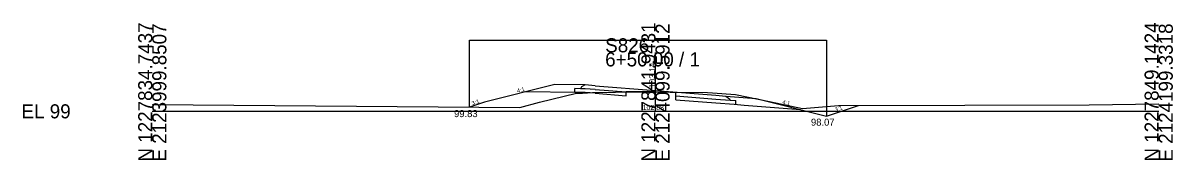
# Model space of a CAD drawing. Extents: x 2118382 to 2118616, y 1213030 to 1222057.
# Drawn here: x 2118381.9 to 2118610.4, y 1217030.1 to 1217057.4 of the extents above; entities that cross this region are included whole.
import ezdxf

# ---------------------------------------------------------------- set-up
doc = ezdxf.new("R2010")
doc.units = 0
for name, color, linetype in [('XS_CELL', 7, 'Continuous'), ('XS_M_DITCH', 7, 'Continuous'), ('XS_P_FINISHED_GRADE', 7, 'Continuous'), ('XS_P_FINISHED_GRADE_ELEV_TX', 7, 'Continuous'), ('XS_P_SUBGRADE_GRANULAR', 7, 'Continuous'), ('XS_P_SUBGRADE_LEVELING', 7, 'Continuous'), ('XS_P_SUBGRADE_PAVEMENT', 7, 'Continuous'), ('XS_P_TX_DCH', 7, 'Continuous'), ('XS_P_TX_FS_BS', 7, 'Continuous'), ('XS_X_GROUND', 7, 'Continuous'), ('XS_X_GROUND_TX', 7, 'Continuous')]:
    doc.layers.add(name, color=color, linetype=linetype)

msp = doc.modelspace()

# ---------------------------------------------------------------- linework, layer by layer
at = {"layer": 'XS_CELL'}
for p, q in [((2118507.6, 1217039.8), (2118507.6, 1217051.54)), ((2118407.6, 1217039.8), (2118507.6, 1217039.8)), ((2118507.6, 1217039.8), (2118607.6, 1217039.8))]:
    msp.add_line(p, q, dxfattribs=at)
at = {"layer": 'XS_M_DITCH'}
for p, q in [((2118470.66, 1217040.63), (2118470.66, 1217053.94)), ((2118470.66, 1217053.94), (2118541.6, 1217053.94)), ((2118541.6, 1217053.94), (2118541.6, 1217038.87))]:
    msp.add_line(p, q, dxfattribs=at)
at = {"layer": 'XS_P_FINISHED_GRADE'}
for p, q in [((2118487.6, 1217045.11), (2118473.6, 1217041.61)), ((2118493.6, 1217045.05), (2118487.6, 1217045.11)), ((2118495.6, 1217044.89), (2118493.6, 1217045.05)), ((2118495.6, 1217044.89), (2118507.6, 1217043.94)), ((2118507.6, 1217043.94), (2118519.6, 1217042.99)), ((2118473.6, 1217041.61), (2118470.66, 1217040.63)), ((2118519.6, 1217042.99), (2118521.6, 1217042.84)), ((2118521.6, 1217042.84), (2118527.6, 1217042.36)), ((2118527.6, 1217042.36), (2118541.6, 1217038.87)), ((2118541.6, 1217038.87), (2118547.93, 1217040.98))]:
    msp.add_line(p, q, dxfattribs=at)
at = {"layer": 'XS_P_SUBGRADE_GRANULAR'}
for p, q in [((2118491.6, 1217043.57), (2118481.82, 1217043.67)), ((2118491.6, 1217043.57), (2118491.6, 1217044.32)), ((2118492.69, 1217044.31), (2118491.6, 1217044.32)), ((2118493.6, 1217043.55), (2118491.6, 1217043.57)), ((2118495.6, 1217043.39), (2118493.6, 1217043.55)), ((2118495.6, 1217043.39), (2118501.78, 1217042.9)), ((2118511.67, 1217042.12), (2118511.67, 1217042.87)), ((2118511.67, 1217042.12), (2118519.6, 1217041.49)), ((2118519.6, 1217041.49), (2118523.22, 1217041.21)), ((2118522.45, 1217042.02), (2118523.6, 1217041.93)), ((2118523.6, 1217041.18), (2118523.6, 1217041.93)), ((2118523.22, 1217041.21), (2118525.22, 1217041.05)), ((2118525.22, 1217041.05), (2118536.4, 1217040.17))]:
    msp.add_line(p, q, dxfattribs=at)
at = {"layer": 'XS_P_SUBGRADE_LEVELING'}
for p, q in [((2118504.25, 1217043.69), (2118501.78, 1217043.65)), ((2118506.02, 1217043.72), (2118504.25, 1217043.69)), ((2118506.81, 1217043.71), (2118506.02, 1217043.72)), ((2118507.6, 1217043.69), (2118506.81, 1217043.71)), ((2118507.6, 1217043.69), (2118510.55, 1217043.64)), ((2118510.55, 1217043.64), (2118511.47, 1217043.62)), ((2118511.47, 1217043.62), (2118511.67, 1217043.62))]:
    msp.add_line(p, q, dxfattribs=at)
at = {"layer": 'XS_P_SUBGRADE_PAVEMENT'}
for p, q in [((2118492.89, 1217044.65), (2118492.69, 1217044.31)), ((2118493.6, 1217044.3), (2118492.69, 1217044.31)), ((2118493.6, 1217045.05), (2118492.89, 1217044.65)), ((2118495.6, 1217044.14), (2118493.6, 1217044.3)), ((2118495.6, 1217044.14), (2118501.78, 1217043.65)), ((2118501.78, 1217042.9), (2118501.78, 1217043.65)), ((2118511.67, 1217042.87), (2118511.67, 1217043.62)), ((2118511.67, 1217042.87), (2118519.6, 1217042.24)), ((2118519.6, 1217042.24), (2118522.45, 1217042.02)), ((2118521.6, 1217042.84), (2118522.28, 1217042.32)), ((2118522.28, 1217042.32), (2118522.45, 1217042.02))]:
    msp.add_line(p, q, dxfattribs=at)
at = {"layer": 'XS_X_GROUND'}
for p, q in [((2118493.07, 1217043.42), (2118495.1, 1217043.55)), ((2118495.1, 1217043.55), (2118504.25, 1217043.68)), ((2118504.25, 1217043.68), (2118506.02, 1217043.71)), ((2118506.02, 1217043.71), (2118507.6, 1217043.68)), ((2118507.6, 1217043.68), (2118510.55, 1217043.63)), ((2118510.55, 1217043.63), (2118511.47, 1217043.62)), ((2118511.47, 1217043.62), (2118517.91, 1217043.52)), ((2118517.91, 1217043.52), (2118518.96, 1217043.47)), ((2118480.63, 1217040.55), (2118484.58, 1217041.61)), ((2118484.58, 1217041.61), (2118491.91, 1217043.39)), ((2118491.91, 1217043.39), (2118493.07, 1217043.42)), ((2118518.96, 1217043.47), (2118523.52, 1217043.14)), ((2118523.52, 1217043.14), (2118530.29, 1217041.75)), ((2118530.29, 1217041.75), (2118536.8, 1217040.34)), ((2118593.75, 1217041.1), (2118607.6, 1217041.3)), ((2118407.6, 1217041.15), (2118480.63, 1217040.55)), ((2118536.8, 1217040.34), (2118543.95, 1217040.93)), ((2118543.95, 1217040.93), (2118544.35, 1217040.97)), ((2118544.35, 1217040.97), (2118593.75, 1217041.1))]:
    msp.add_line(p, q, dxfattribs=at)

# ---------------------------------------------------------------- texts
at = {"layer": 'XS_CELL'}
for s, p in [('N 1227834.7437', (2118407.6, 1217029.8)), ('N 1227841.9431', (2118507.6, 1217029.8)), ('N 1227849.1424', (2118607.6, 1217029.8)), ('E 2123999.8507', (2118410.4, 1217029.8)), ('E 2124099.5912', (2118510.4, 1217029.8)), ('E 2124199.3318', (2118610.4, 1217029.8))]:
    msp.add_text(s, height=2.8, rotation=90, dxfattribs=at).set_placement(p)
for s, p in [('S826', (2118497.6, 1217051.54)), ('6+50.00 / 1', (2118497.6, 1217048.74)), ('EL 99', (2118381.6, 1217038.4))]:
    msp.add_text(s, height=2.8, dxfattribs=at).set_placement(p)
at = {"layer": 'XS_P_FINISHED_GRADE_ELEV_TX'}
msp.add_text(' 103.14', height=1.25, rotation=90, dxfattribs=at).set_placement((2118507.6, 1217043.94))
at = {"layer": 'XS_P_TX_DCH'}
for s, p in [('99.83', (2118467.57, 1217038.65)), ('98.07', (2118538.5, 1217036.94))]:
    msp.add_text(s, height=1.4, dxfattribs=at).set_placement(p)
at = {"layer": 'XS_P_TX_FS_BS'}
for s, rotation, p in [('4:1', 14.0157, (2118480.18, 1217043.48)), ('3:1', 18.4087, (2118471.23, 1217041)), ('4:1', 345.988, (2118532.76, 1217041.29)), ('3:1', 18.404, (2118543.39, 1217039.72))]:
    msp.add_text(s, height=0.8, rotation=rotation, dxfattribs=at).set_placement(p)
at = {"layer": 'XS_X_GROUND_TX'}
msp.add_text('102.88', height=1, dxfattribs=at).set_placement((2118505.05, 1217040.06))

doc.saveas('drawing.dxf')
